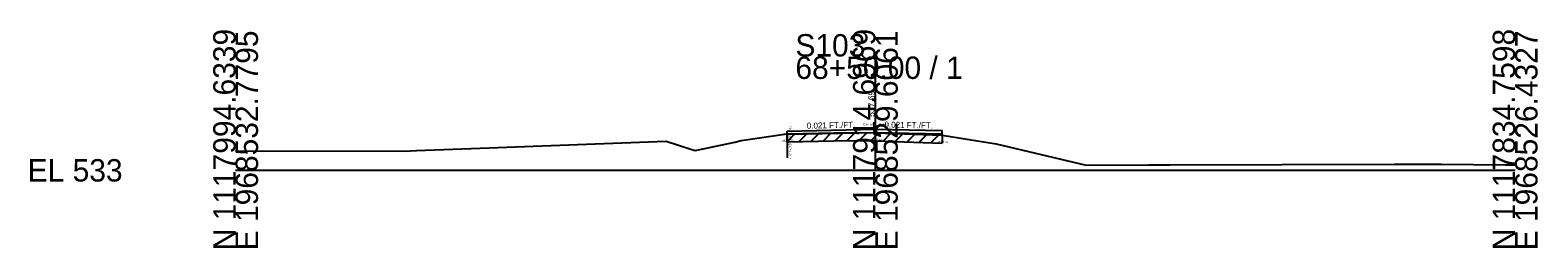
# Model space of a CAD drawing. Extents: x -26 to 163, y -10 to 24018.
# Drawn here: x -25.7 to 162.8, y 16490.3 to 16517.5 of the extents above; entities that cross this region are included whole.
import ezdxf

# ---------------------------------------------------------------- set-up
doc = ezdxf.new("R2010")
doc.units = 0
for name, color, linetype in [('RD_GPK_XS_Cell', 7, 'Continuous'), ('RD_XS_ExGround', 7, 'Continuous'), ('RD_XS_ExPaveRet', 7, 'Continuous'), ('RD_XS_Misc_Line', 7, 'Continuous'), ('RD_XS_PaveOvlay_CP', 7, 'Continuous'), ('RD_XS_TX_Elev_EX', 7, 'Continuous'), ('RD_XS_TX_ExEOP', 7, 'Continuous'), ('RD_XS_TX_Notes', 7, 'Continuous'), ('RD_XS_TX_Profile', 7, 'Continuous'), ('RD_XS_TX_Slope', 7, 'Continuous')]:
    doc.layers.add(name, color=color, linetype=linetype)

msp = doc.modelspace()

# ---------------------------------------------------------------- linework, layer by layer
at = {"layer": 'RD_GPK_XS_Cell'}
for p, q in [((80, 16500), (80, 16514.23)), ((0, 16500), (80, 16500)), ((80, 16500), (160, 16500))]:
    msp.add_line(p, q, dxfattribs=at)
at = {"layer": 'RD_XS_ExGround'}
msp.add_lwpolyline([(0, 16502.45), (21.11, 16502.4), (22.61, 16502.46), (30.6, 16502.76), (53.84, 16503.63), (56.94, 16502.63), (57.45, 16502.48), (62.41, 16503.54), (63.23, 16503.71), (68.62, 16504.53), (68.97, 16504.58), (74.8, 16504.68), (78.41, 16504.74), (80, 16504.69), (88.37, 16504.41), (95.11, 16503.32), (106.36, 16500.64), (114.19, 16500.7), (116.83, 16500.7), (144.92, 16500.79), (150.74, 16500.78), (158.78, 16500.7), (160, 16500.69)], dxfattribs=at)
at = {"layer": 'RD_XS_ExPaveRet'}
for p, q in [((68.97, 16503.58), (69.99, 16504.6)), ((68.97, 16503.58), (68.97, 16504.58)), ((70.47, 16503.61), (71.49, 16504.62)), ((71.97, 16503.63), (72.99, 16504.65)), ((73.47, 16503.66), (74.49, 16504.67)), ((74.97, 16503.68), (75.99, 16504.7)), ((76.47, 16503.71), (77.49, 16504.73)), ((77.97, 16503.74), (78.96, 16504.72)), ((79.47, 16503.71), (80.44, 16504.68)), ((80.97, 16503.66), (81.94, 16504.63)), ((82.47, 16503.61), (83.44, 16504.58)), ((83.97, 16503.56), (84.94, 16504.53)), ((85.47, 16503.51), (86.44, 16504.48)), ((86.97, 16503.46), (87.94, 16504.43)), ((88.37, 16504.41), (88.37, 16503.41)), ((68.97, 16503.58), (74.8, 16503.68)), ((74.8, 16503.68), (78.41, 16503.74)), ((78.41, 16503.74), (80, 16503.69)), ((80, 16503.69), (88.37, 16503.41))]:
    msp.add_line(p, q, dxfattribs=at)
at = {"layer": 'RD_XS_Misc_Line'}
msp.add_line((68.97, 16504.58), (68.97, 16501.58), dxfattribs=at)
at = {"layer": 'RD_XS_PaveOvlay_CP'}
for p, q in [((68.97, 16504.9), (80, 16505.13)), ((68.97, 16504.58), (68.97, 16504.9)), ((80, 16504.69), (68.97, 16504.46)), ((80, 16505.13), (88.37, 16504.96)), ((88.37, 16504.52), (80, 16504.69)), ((88.37, 16504.41), (88.37, 16504.96))]:
    msp.add_line(p, q, dxfattribs=at)

# ---------------------------------------------------------------- texts
at = {"layer": 'RD_GPK_XS_Cell'}
for s, p in [('N 1117994.6339', (0, 16490)), ('N 1117914.6969', (80, 16490)), ('N 1117834.7598', (160, 16490)), ('E 1968532.7795', (2.8, 16490)), ('E 1968529.6061', (82.8, 16490)), ('E 1968526.4327', (162.8, 16490))]:
    msp.add_text(s, height=2.8, rotation=90, dxfattribs=at).set_placement(p)
for s, p in [('S103', (70, 16514.23)), ('68+50.00 / 1', (70, 16511.43)), ('EL 533', (-26, 16498.6))]:
    msp.add_text(s, height=2.8, dxfattribs=at).set_placement(p)
at = {"layer": 'RD_XS_TX_Elev_EX'}
msp.add_text('537.69', height=0.8, rotation=90, dxfattribs=at).set_placement((79.9, 16506.69))
at = {"layer": 'RD_XS_TX_ExEOP'}
for s, p in [('EOP-L', (68.92, 16504.9)), ('EOP-R', (88.32, 16504.96))]:
    msp.add_text(s, height=0.1, rotation=270, dxfattribs=at).set_placement(p)
at = {"layer": 'RD_XS_TX_Notes'}
msp.add_text(' Min. Distance @CP = -0.12', height=0.25, rotation=270, dxfattribs=at).set_placement((69.22, 16505.68))
for s, p in [('Elev. @CL = 538.13', (78.48, 16505.63)), (' dE= 0.32', (68.26, 16503.58)), (' dE= 0.44', (79.29, 16503.69)), (' dE= 0.54', (87.65, 16503.41))]:
    msp.add_text(s, height=0.25, dxfattribs=at).set_placement(p)
at = {"layer": 'RD_XS_TX_Profile'}
msp.add_text('CL', height=0.25, dxfattribs=at).set_placement((79.77, 16505.13))
at = {"layer": 'RD_XS_TX_Slope'}
for rotation, p in [(1.1916, (71.43, 16505.2)), (358.8084, (81.13, 16505.36))]:
    msp.add_text('0.021 FT./FT.', height=0.75, rotation=rotation, dxfattribs=at).set_placement(p)

doc.saveas('drawing.dxf')
